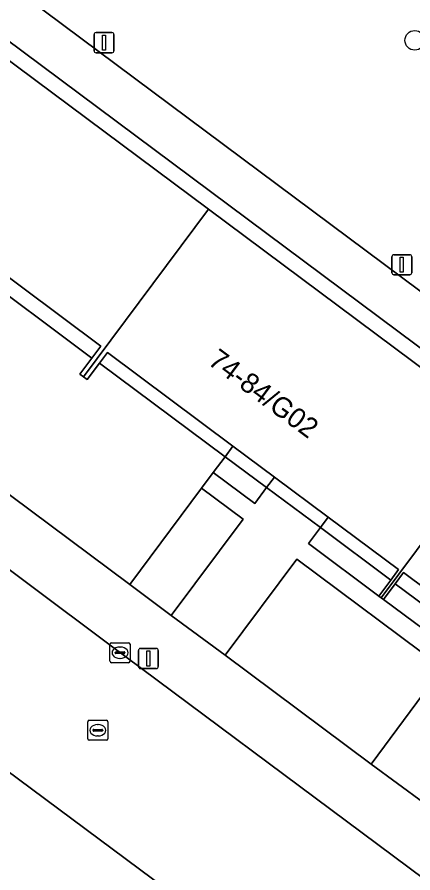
# Model space of a CAD drawing. Extents: x 160023 to 161302, y 384750 to 385707.
# Drawn here: x 160349.26 to 160368.97, y 385258.63 to 385301.25 of the extents above; entities that cross this region are included whole.
import ezdxf

# ---------------------------------------------------------------- set-up
doc = ezdxf.new("R2010")
doc.units = 0
for name, color, linetype in [('IMGEO_Boom', 7, 'Continuous'), ('IMGEO_Groenvoorziening', 7, 'Continuous'), ('IMGEO_Kolk', 7, 'Continuous'), ('IMGEO_Lichtmast', 7, 'Continuous'), ('IMGEO_Pand', 7, 'Continuous'), ('IMGEO_Pand_nummerreeks', 7, 'Continuous'), ('IMGEO_Rijbaan_lokaal_gesloten', 7, 'Continuous'), ('IMGEO_Rijbaan_lokaal_open', 7, 'Continuous'), ('IMGEO_Rioolput', 7, 'Continuous'), ('IMGEO_Voetpad_open', 7, 'Continuous')]:
    doc.layers.add(name, color=color, linetype=linetype)

msp = doc.modelspace()

# ---------------------------------------------------------------- linework, layer by layer
at = {"layer": 'IMGEO_Boom'}
msp.add_circle((160369.06, 385300.093), 0.489, dxfattribs=at)
at = {"layer": 'IMGEO_Groenvoorziening'}
for points in [[(160357.697, 385345.725), (160354.718, 385341.545), (160353.056, 385342.687), (160345.613, 385332.114), (160334.44, 385339.82), (160325.57, 385327.213), (160343.235, 385314.042), (160339.974, 385309.507), (160394.21, 385269.049), (160405.856, 385284.994), (160415.293, 385297.914), (160400.011, 385309.258), (160402.452, 385312.526), (160390.707, 385321.238), (160390.121, 385320.417), (160384.461, 385324.633), (160385.071, 385325.42)], [(160361.683, 385277.817), (160362.076, 385278.345), (160360.008, 385279.886), (160359.613, 385279.356)], [(160359.613, 385279.356), (160359.026, 385278.568), (160361.094, 385277.027), (160361.683, 385277.817)], [(160356.935, 385271.446), (160360.514, 385276.247), (160358.446, 385277.789), (160354.867, 385272.988)], [(160364.75, 385276.351), (160364.359, 385275.827), (160367.871, 385273.215), (160368.259, 385273.735)], [(160364.359, 385275.827), (160363.767, 385275.032), (160367.276, 385272.416), (160367.871, 385273.215)], [(160370.45, 385268.834), (160363.186, 385274.25), (160359.618, 385269.465), (160366.883, 385264.049)], [(160368.082, 385273.02), (160371.613, 385270.397), (160372.029, 385270.955), (160368.503, 385273.584)], [(160368.082, 385273.02), (160367.505, 385272.245), (160371.032, 385269.617), (160371.613, 385270.397)]]:
    msp.add_lwpolyline(points, close=True, dxfattribs=at)
at = {"layer": 'IMGEO_Kolk'}
for p, q in [((160353.885, 385269.167), (160353.885, 385270.019)), ((160353.96, 385270.093), (160354.812, 385270.093)), ((160354.886, 385270.019), (160354.886, 385269.167)), ((160354.144, 385269.587), (160354.144, 385269.599)), ((160354.582, 385269.55), (160354.184, 385269.55)), ((160354.187, 385269.636), (160354.585, 385269.636)), ((160354.373, 385269.873), (160354.398, 385269.873)), ((160354.628, 385269.599), (160354.628, 385269.587)), ((160354.812, 385269.093), (160353.96, 385269.093)), ((160354.396, 385269.313), (160354.371, 385269.313))]:
    msp.add_line(p, q, dxfattribs=at)
for points in [[(160353.885, 385269.167), (160353.885, 385270.019)], [(160353.96, 385270.093), (160354.812, 385270.093)], [(160354.886, 385270.019), (160354.886, 385269.167)], [(160354.812, 385269.093), (160353.96, 385269.093)]]:
    msp.add_lwpolyline(points, dxfattribs=at)
for centre, radius, start, end in [((160353.962, 385270.017), 0.0765, 91.552, 178.448), ((160353.962, 385270.017), 0.0765, 91.552, 178.448), ((160354.81, 385270.017), 0.0765, 1.552, 88.448), ((160354.81, 385270.017), 0.0765, 1.552, 88.448), ((160354.184, 385269.596), 0.0403, 85.8775, 175.7526), ((160354.181, 385269.586), 0.0366, 178.938, 274.7102), ((160354.585, 385269.593), 0.043, 264.8664, 352.4533), ((160354.589, 385269.598), 0.0386, 1.7309, 96.639), ((160353.962, 385269.169), 0.0765, 181.552, 268.448), ((160353.962, 385269.169), 0.0765, 181.552, 268.448), ((160354.81, 385269.169), 0.0765, 271.552, 358.448), ((160354.81, 385269.169), 0.0765, 271.552, 358.448)]:
    msp.add_arc(centre, radius, start, end, dxfattribs=at)
for centre, major_axis, ratio, start_param, end_param in [((160354.372, 385269.593), (-0.387, 0.002), 0.722429, 4.712389, 7.853982), ((160354.397, 385269.593), (-0.39, 0.002), 0.717154, 1.570796, 4.712389)]:
    msp.add_ellipse(centre, major_axis=major_axis, ratio=ratio, start_param=start_param, end_param=end_param, dxfattribs=at)
at = {"layer": 'IMGEO_Lichtmast'}
for p, q in [((160353.091, 385299.577), (160353.091, 385300.377)), ((160353.091, 385300.377), (160353.091, 385299.577)), ((160353.191, 385300.477), (160353.981, 385300.477)), ((160353.981, 385300.477), (160353.191, 385300.477)), ((160354.081, 385300.377), (160354.081, 385299.577)), ((160354.081, 385299.577), (160354.081, 385300.377)), ((160353.981, 385299.477), (160353.191, 385299.477)), ((160353.191, 385299.477), (160353.981, 385299.477)), ((160367.92, 385288.516), (160367.92, 385289.316)), ((160367.92, 385289.316), (160367.92, 385288.516)), ((160368.02, 385289.416), (160368.81, 385289.416)), ((160368.81, 385289.416), (160368.02, 385289.416)), ((160368.91, 385289.316), (160368.91, 385288.516)), ((160368.91, 385288.516), (160368.91, 385289.316)), ((160368.81, 385288.416), (160368.02, 385288.416)), ((160368.02, 385288.416), (160368.81, 385288.416)), ((160355.301, 385268.905), (160355.301, 385269.705)), ((160355.301, 385269.705), (160355.301, 385268.905)), ((160355.401, 385269.805), (160356.191, 385269.805)), ((160356.191, 385269.805), (160355.401, 385269.805)), ((160356.291, 385269.705), (160356.291, 385268.905)), ((160356.291, 385268.905), (160356.291, 385269.705)), ((160356.191, 385268.805), (160355.401, 385268.805)), ((160355.401, 385268.805), (160356.191, 385268.805))]:
    msp.add_line(p, q, dxfattribs=at)
for points in [[(160353.511, 385300.352), (160353.661, 385300.352), (160353.661, 385299.602), (160353.511, 385299.602), (160353.511, 385300.352)], [(160368.34, 385289.291), (160368.49, 385289.291), (160368.49, 385288.541), (160368.34, 385288.541), (160368.34, 385289.291)], [(160355.721, 385269.68), (160355.871, 385269.68), (160355.871, 385268.93), (160355.721, 385268.93), (160355.721, 385269.68)]]:
    msp.add_lwpolyline(points, dxfattribs=at)
for centre, start, end in [((160353.191, 385300.377), 90, 180), ((160353.191, 385300.377), 90, 180), ((160353.981, 385300.377), 0, 90), ((160353.981, 385300.377), 360, 90), ((160353.191, 385299.577), 180, 270), ((160353.191, 385299.577), 180, 270), ((160353.981, 385299.577), 270, 0), ((160353.981, 385299.577), 270, 0), ((160368.02, 385289.316), 90, 180), ((160368.02, 385289.316), 90, 180), ((160368.81, 385289.316), 0, 90), ((160368.81, 385289.316), 360, 90), ((160368.02, 385288.516), 180, 270), ((160368.02, 385288.516), 180, 270), ((160368.81, 385288.516), 270, 0), ((160368.81, 385288.516), 270, 0), ((160355.401, 385269.705), 90, 180), ((160355.401, 385269.705), 90, 180), ((160356.191, 385269.705), 0, 90), ((160356.191, 385269.705), 360, 90), ((160355.401, 385268.905), 180, 270), ((160355.401, 385268.905), 180, 270), ((160356.191, 385268.905), 270, 0), ((160356.191, 385268.905), 270, 0)]:
    msp.add_arc(centre, 0.1, start, end, dxfattribs=at)
at = {"layer": 'IMGEO_Pand'}
for points in [[(160358.796, 385291.679), (160344.055, 385302.669), (160337.856, 385294.359), (160337.96, 385294.281), (160338.543, 385295.063), (160338.969, 385295.634), (160342.606, 385292.923), (160345.176, 385291.006), (160347.248, 385289.462), (160347.481, 385289.288), (160353.426, 385284.856), (160352.984, 385284.263), (160352.387, 385283.462), (160352.567, 385283.328)], [(160358.796, 385291.679), (160352.567, 385283.328), (160352.746, 385283.194), (160353.355, 385284.011), (160353.756, 385284.548), (160360.008, 385279.886), (160362.076, 385278.345), (160364.75, 385276.351), (160368.259, 385273.735), (160367.871, 385273.215), (160367.276, 385272.416), (160367.391, 385272.33), (160373.594, 385280.647)], [(160388.24, 385269.728), (160373.594, 385280.647), (160367.391, 385272.33), (160367.505, 385272.245), (160368.082, 385273.02), (160368.503, 385273.584), (160372.029, 385270.955), (160374.645, 385269.006), (160376.814, 385267.388), (160383.043, 385262.745), (160382.64, 385262.204), (160382.042, 385261.402), (160382.307, 385261.205), (160384.836, 385264.597), (160388.963, 385270.133), (160388.692, 385270.335)]]:
    msp.add_lwpolyline(points, close=True, dxfattribs=at)
at = {"layer": 'IMGEO_Rijbaan_lokaal_gesloten'}
msp.add_lwpolyline([(160323.03, 385282.896), (160343.93, 385267.299), (160357.361, 385257.313), (160367.132, 385250), (160375.681, 385243.601), (160380.549, 385250.106), (160353.887, 385269.963), (160333.903, 385284.92), (160316.228, 385298.079), (160311.4, 385291.54)], close=True, dxfattribs=at)
at = {"layer": 'IMGEO_Rijbaan_lokaal_open'}
msp.add_lwpolyline([(160357.361, 385257.313), (160343.93, 385267.299)], dxfattribs=at)
at = {"layer": 'IMGEO_Rioolput'}
for p, q in [((160352.78, 385265.305), (160352.78, 385266.157)), ((160352.855, 385266.231), (160353.707, 385266.231)), ((160353.781, 385266.157), (160353.781, 385265.305)), ((160353.039, 385265.725), (160353.039, 385265.737)), ((160353.477, 385265.688), (160353.079, 385265.688)), ((160353.082, 385265.774), (160353.48, 385265.774)), ((160353.268, 385266.011), (160353.293, 385266.011)), ((160353.523, 385265.737), (160353.523, 385265.725)), ((160353.707, 385265.231), (160352.855, 385265.231)), ((160353.291, 385265.451), (160353.266, 385265.451))]:
    msp.add_line(p, q, dxfattribs=at)
for points in [[(160352.78, 385265.305), (160352.78, 385266.157)], [(160352.855, 385266.231), (160353.707, 385266.231)], [(160353.781, 385266.157), (160353.781, 385265.305)], [(160353.707, 385265.231), (160352.855, 385265.231)]]:
    msp.add_lwpolyline(points, dxfattribs=at)
for centre, radius, start, end in [((160352.857, 385266.155), 0.0765, 91.552, 178.448), ((160352.857, 385266.155), 0.0765, 91.552, 178.448), ((160353.705, 385266.155), 0.0765, 1.552, 88.448), ((160353.705, 385266.155), 0.0765, 1.552, 88.448), ((160353.079, 385265.734), 0.0403, 85.8775, 175.7526), ((160353.076, 385265.724), 0.0366, 178.938, 274.7102), ((160353.48, 385265.731), 0.043, 264.8664, 352.4533), ((160353.484, 385265.736), 0.0386, 1.7309, 96.639), ((160352.857, 385265.307), 0.0765, 181.552, 268.448), ((160352.857, 385265.307), 0.0765, 181.552, 268.448), ((160353.705, 385265.307), 0.0765, 271.552, 358.448), ((160353.705, 385265.307), 0.0765, 271.552, 358.448)]:
    msp.add_arc(centre, radius, start, end, dxfattribs=at)
for centre, major_axis, ratio, start_param, end_param in [((160353.267, 385265.731), (-0.387, 0.002), 0.722429, 4.712389, 7.853982), ((160353.292, 385265.731), (-0.39, 0.002), 0.717154, 1.570796, 4.712389)]:
    msp.add_ellipse(centre, major_axis=major_axis, ratio=ratio, start_param=start_param, end_param=end_param, dxfattribs=at)
at = {"layer": 'IMGEO_Voetpad_open'}
for points in [[(160394.21, 385269.049), (160339.974, 385309.507), (160321.516, 385323.274), (160320.296, 385321.498), (160328.67, 385315.311), (160324.315, 385309.421), (160325.396, 385308.625), (160329.671, 385314.36), (160329.975, 385314.134), (160388.692, 385270.335)], [(160371.677, 385260.495), (160369.507, 385262.112), (160366.883, 385264.049), (160359.618, 385269.465), (160356.935, 385271.446), (160354.867, 385272.988), (160342.067, 385282.531), (160340.004, 385284.069), (160337.448, 385286.002), (160330.067, 385291.504), (160327.484, 385293.444), (160325.253, 385295.108), (160318.811, 385299.794), (160312.211, 385304.595), (160308.844, 385305.664)], [(160311.165, 385301.848), (160313.407, 385300.179), (160316.228, 385298.079), (160333.903, 385284.92), (160353.887, 385269.963), (160380.549, 385250.106), (160380.691, 385250), (160383.33, 385248.034), (160387.482, 385245.014), (160388.218, 385244.48), (160388.547, 385243.785), (160388.572, 385242.838)]]:
    msp.add_lwpolyline(points, dxfattribs=at)
for points in [[(160358.796, 385291.679), (160373.594, 385280.647), (160388.24, 385269.728), (160388.692, 385270.335), (160329.975, 385314.134), (160329.511, 385313.511), (160344.055, 385302.669)], [(160347.481, 385289.288), (160347.248, 385289.462), (160346.813, 385288.878), (160352.984, 385284.263), (160353.426, 385284.856)], [(160353.355, 385284.011), (160352.746, 385283.194), (160352.567, 385283.328), (160352.387, 385283.462), (160352.984, 385284.263), (160346.813, 385288.878), (160346.234, 385288.103), (160345.662, 385287.338), (160342.067, 385282.531), (160354.867, 385272.988), (160358.446, 385277.789), (160359.026, 385278.568), (160359.613, 385279.356)], [(160359.613, 385279.356), (160360.008, 385279.886), (160353.756, 385284.548), (160353.355, 385284.011)], [(160367.276, 385272.416), (160363.767, 385275.032), (160364.359, 385275.827), (160361.683, 385277.817), (160361.094, 385277.027), (160359.026, 385278.568), (160358.446, 385277.789), (160360.514, 385276.247), (160356.935, 385271.446), (160359.618, 385269.465), (160363.186, 385274.25), (160370.45, 385268.834), (160366.883, 385264.049), (160369.507, 385262.112), (160373.07, 385266.892), (160375.24, 385265.275), (160375.818, 385266.05), (160373.648, 385267.668), (160374.232, 385268.451), (160371.613, 385270.397), (160371.032, 385269.617), (160367.505, 385272.245), (160367.391, 385272.33)], [(160364.359, 385275.827), (160364.75, 385276.351), (160362.076, 385278.345), (160361.683, 385277.817)]]:
    msp.add_lwpolyline(points, close=True, dxfattribs=at)

# ---------------------------------------------------------------- texts
at = {"layer": 'IMGEO_Pand_nummerreeks'}
msp.add_text('74-84/G02', height=1, rotation=323.2929, dxfattribs=at).set_placement((160358.709, 385283.998))

doc.saveas('drawing.dxf')
